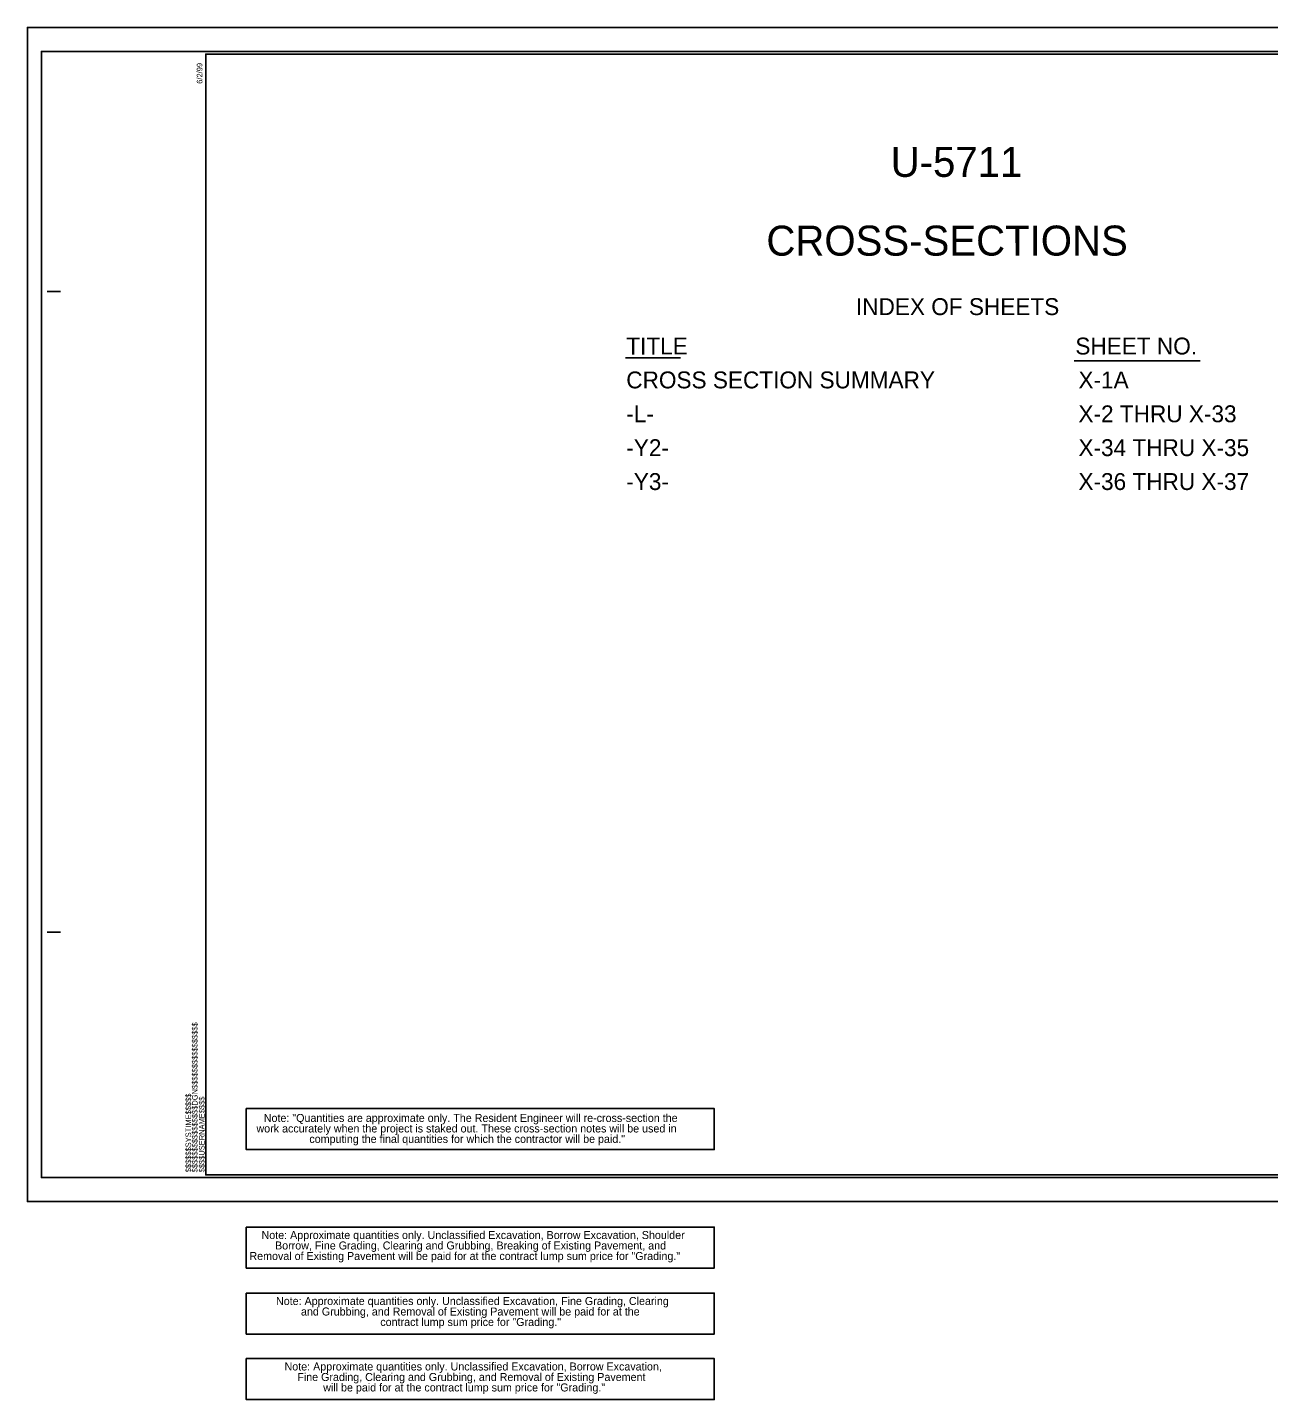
# Model space of a CAD drawing. Extents: x -19 to 363, y -37 to 220.
# Drawn here: x -19 to 213.6, y -37.1 to 220 of the extents above; entities that cross this region are included whole.
import ezdxf

# ---------------------------------------------------------------- set-up
doc = ezdxf.new("R2010")
doc.units = 0
for name, color, linetype in [('Prop Grid Mask', 7, 'Continuous'), ('Prop XSC Text', 7, 'Continuous'), ('Sheet Cutting Line CELL', 7, 'Continuous'), ('Sheet Plot Border Inside CELL', 7, 'Continuous'), ('Sheet Plot Border Outside CELL', 7, 'Continuous'), ('Sheet Summary Combination CELL', 7, 'Continuous'), ('Sheet Typical CELL', 7, 'Continuous')]:
    doc.layers.add(name, color=color, linetype=linetype)

msp = doc.modelspace()

# ---------------------------------------------------------------- linework, layer by layer
at = {"layer": 'Prop Grid Mask'}
for points in [[(22.04, 17.43), (109.72, 17.43), (109.72, 9.74), (22.04, 9.74)], [(22.04, -4.77), (109.72, -4.77), (109.72, -12.45), (22.04, -12.45)], [(22.04, -17.13), (109.72, -17.13), (109.72, -24.82), (22.04, -24.82)], [(22.04, -29.4), (109.72, -29.4), (109.72, -37.09), (22.04, -37.09)]]:
    msp.add_lwpolyline(points, close=True, dxfattribs=at)
at = {"layer": 'Sheet Cutting Line CELL'}
for p, q in [((317.85, 220.01), (-18.95, 220.01)), ((-18.95, 220.01), (-18.95, 0.01)), ((-18.95, 0.01), (317.85, 0.01))]:
    msp.add_line(p, q, dxfattribs=at)
at = {"layer": 'Sheet Plot Border Inside CELL'}
msp.add_lwpolyline([(316.95, 215.52), (-16.35, 215.52), (-16.35, 4.5), (316.95, 4.5)], close=True, dxfattribs=at)
at = {"layer": 'Sheet Plot Border Outside CELL'}
msp.add_lwpolyline([(317.85, 220.01), (-18.95, 220.01), (-18.95, 0.01), (317.85, 0.01)], close=True, dxfattribs=at)
at = {"layer": 'Sheet Summary Combination CELL'}
for p, q in [((93.08, 158.09), (103.37, 158.09)), ((177.16, 157.57), (200.73, 157.57))]:
    msp.add_line(p, q, dxfattribs=at)
at = {"layer": 'Sheet Typical CELL'}
for p, q in [((-15.25, 170.51), (-12.75, 170.51)), ((-15.25, 50.51), (-12.75, 50.51)), ((14.45, 5.01), (14.45, 5.01)), ((14.45, 5.01), (14.45, 5.01)), ((14.45, 5.01), (14.45, 5.01)), ((14.45, 5.01), (14.45, 5.01)), ((14.45, 5.01), (14.45, 5.01)), ((14.45, 5.01), (14.45, 5.01))]:
    msp.add_line(p, q, dxfattribs=at)
msp.add_lwpolyline([(314.45, 215.01), (14.45, 215.01), (14.45, 5.01), (314.45, 5.01)], close=True, dxfattribs=at)

# ---------------------------------------------------------------- texts
at = {"layer": 'Prop XSC Text'}
for s, p in [('Note: "Quantities are approximate only. The Resident Engineer will re-cross-section the', (25.32, 14.93)), ('work accurately when the project is staked out. These cross-section notes will be used in', (23.95, 12.96)), ('computing the final quantities for which the contractor will be paid."', (33.86, 11)), ('Note: Approximate quantities only. Unclassified Excavation, Borrow Excavation, Shoulder', (24.9, -7.01)), ('Borrow, Fine Grading, Clearing and Grubbing, Breaking of Existing Pavement, and', (27.43, -8.97)), ('Removal of Existing Pavement will be paid for at the contract lump sum price for "Grading."', (22.63, -10.94)), ('Note: Approximate quantities only. Unclassified Excavation, Fine Grading, Clearing ', (27.61, -19.37)), ('and Grubbing, and Removal of Existing Pavement will be paid for at the ', (32.29, -21.34)), ('contract lump sum price for "Grading."', (47.15, -23.3)), ('Note: Approximate quantities only. Unclassified Excavation, Borrow Excavation, ', (29.21, -31.64)), ('Fine Grading, Clearing and Grubbing, and Removal of Existing Pavement ', (31.6, -33.61)), ('will be paid for at the contract lump sum price for "Grading."', (36.45, -35.57))]:
    msp.add_text(s, height=1.5, dxfattribs=at).set_placement(p)
at = {"layer": 'Sheet Summary Combination CELL'}
for s, height, p in [('U-5711', 5.625, (142.76, 192.01)), ('CROSS-SECTIONS', 5.625, (119.48, 177.25)), ('INDEX OF SHEETS', 3.1641, (136.26, 166.11)), ('TITLE', 3.164, (93.23, 158.73)), ('SHEET NO.', 3.164, (177.36, 158.73)), ('CROSS SECTION SUMMARY', 3.1641, (93.23, 152.38)), ('X-1A', 3.164, (177.94, 152.38)), ('-L-', 3.164, (93.23, 146.03)), ('X-2 THRU X-33', 3.1641, (177.94, 146.03)), ('-Y2-', 3.164, (93.23, 139.69)), ('X-34 THRU X-35', 3.1641, (177.94, 139.69)), ('-Y3-', 3.164, (93.23, 133.34)), ('X-36 THRU X-37 ', 3.1641, (177.94, 133.34))]:
    msp.add_text(s, height=height, rotation=0.0119, dxfattribs=at).set_placement(p)
at = {"layer": 'Sheet Typical CELL'}
for s, p in [('6/2/99', (13.82, 209.46)), ('$$$$$$$$$$$$$$$$DGN$$$$$$$$$$$$$$$$', (12.92, 5.49)), ('$$$$$$SYSTIME$$$$$', (11.71, 5.49)), ('$$$$USERNAME$$$$', (14.23, 5.49))]:
    msp.add_text(s, height=1.05, rotation=90, dxfattribs=at).set_placement(p)

doc.saveas('drawing.dxf')
